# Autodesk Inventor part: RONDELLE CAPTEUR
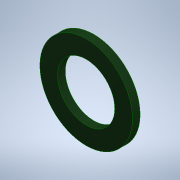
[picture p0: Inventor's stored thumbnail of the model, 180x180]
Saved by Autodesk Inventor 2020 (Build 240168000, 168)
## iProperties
Created: 2003-06
Part Number: RONDELLE CAPTEUR
Material: Générique
Document SubType Name: Modeling
Designer: Bruno
Density: 1 g/cm^3
Appearance: Par défaut
Author: Bruno
Sending System: SolidWorks 2011
Last Author: Professeur
Last Saved: 2014-11-10
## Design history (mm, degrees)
feature "Base-Extrusion"
node "Solide1"
